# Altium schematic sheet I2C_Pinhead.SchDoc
size A4
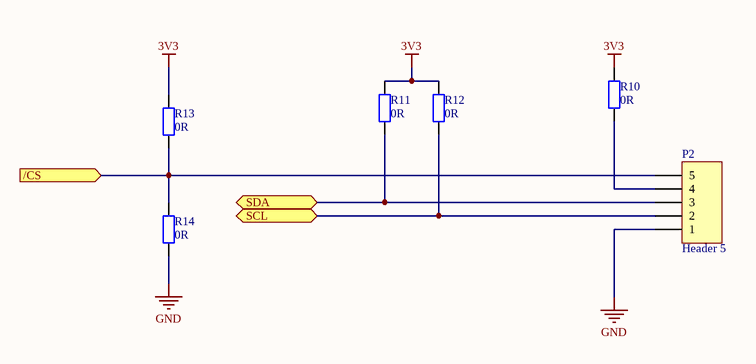
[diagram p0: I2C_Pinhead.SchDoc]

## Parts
P2  Header 5  [HDR1X5]
R10  0R  [RLCDT_1206]
R11  0R  [RLCDT_1206]
R12  0R  [RLCDT_1206]
R13  0R  [RLCDT_1206]
R14  0R  [RLCDT_1206]

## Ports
/CS (in), SCL (bidir), SDA (bidir)

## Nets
3V3: R10.2 R11.2 R12.2 R13.2
GND: P2.1 R14.1
/CS: P2.5 R13.1 R14.2 ; port /CS
SCL: P2.2 R12.1 ; port SCL
SDA: P2.3 R11.1 ; port SDA
NetP2_4: P2.4 R10.1

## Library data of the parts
P2 = Header 5: Header, 5-Pin
R10-R14 = R: Widerstand; W_Erstellt: MRipel; A_Wichtiger_Hinweis: optional; L_Spannung: 50V; H_Temp_min: ?°C; J_Richtpreis_10: 0,00; G_Wird_beigestellt: Nein; A_Update_From_DB: Ja; A_Database_ID: not updated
